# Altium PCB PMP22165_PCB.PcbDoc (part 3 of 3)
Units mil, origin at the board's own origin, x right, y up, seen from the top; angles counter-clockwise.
Board outline 3700 x 3000 mil, 4 copper layers (Top Layer, Signal Layer 1, Signal Layer 2, Bottom Layer), stack 61.634 mil thick; 232 components, 104 nets, 594 pads, 232 vias.
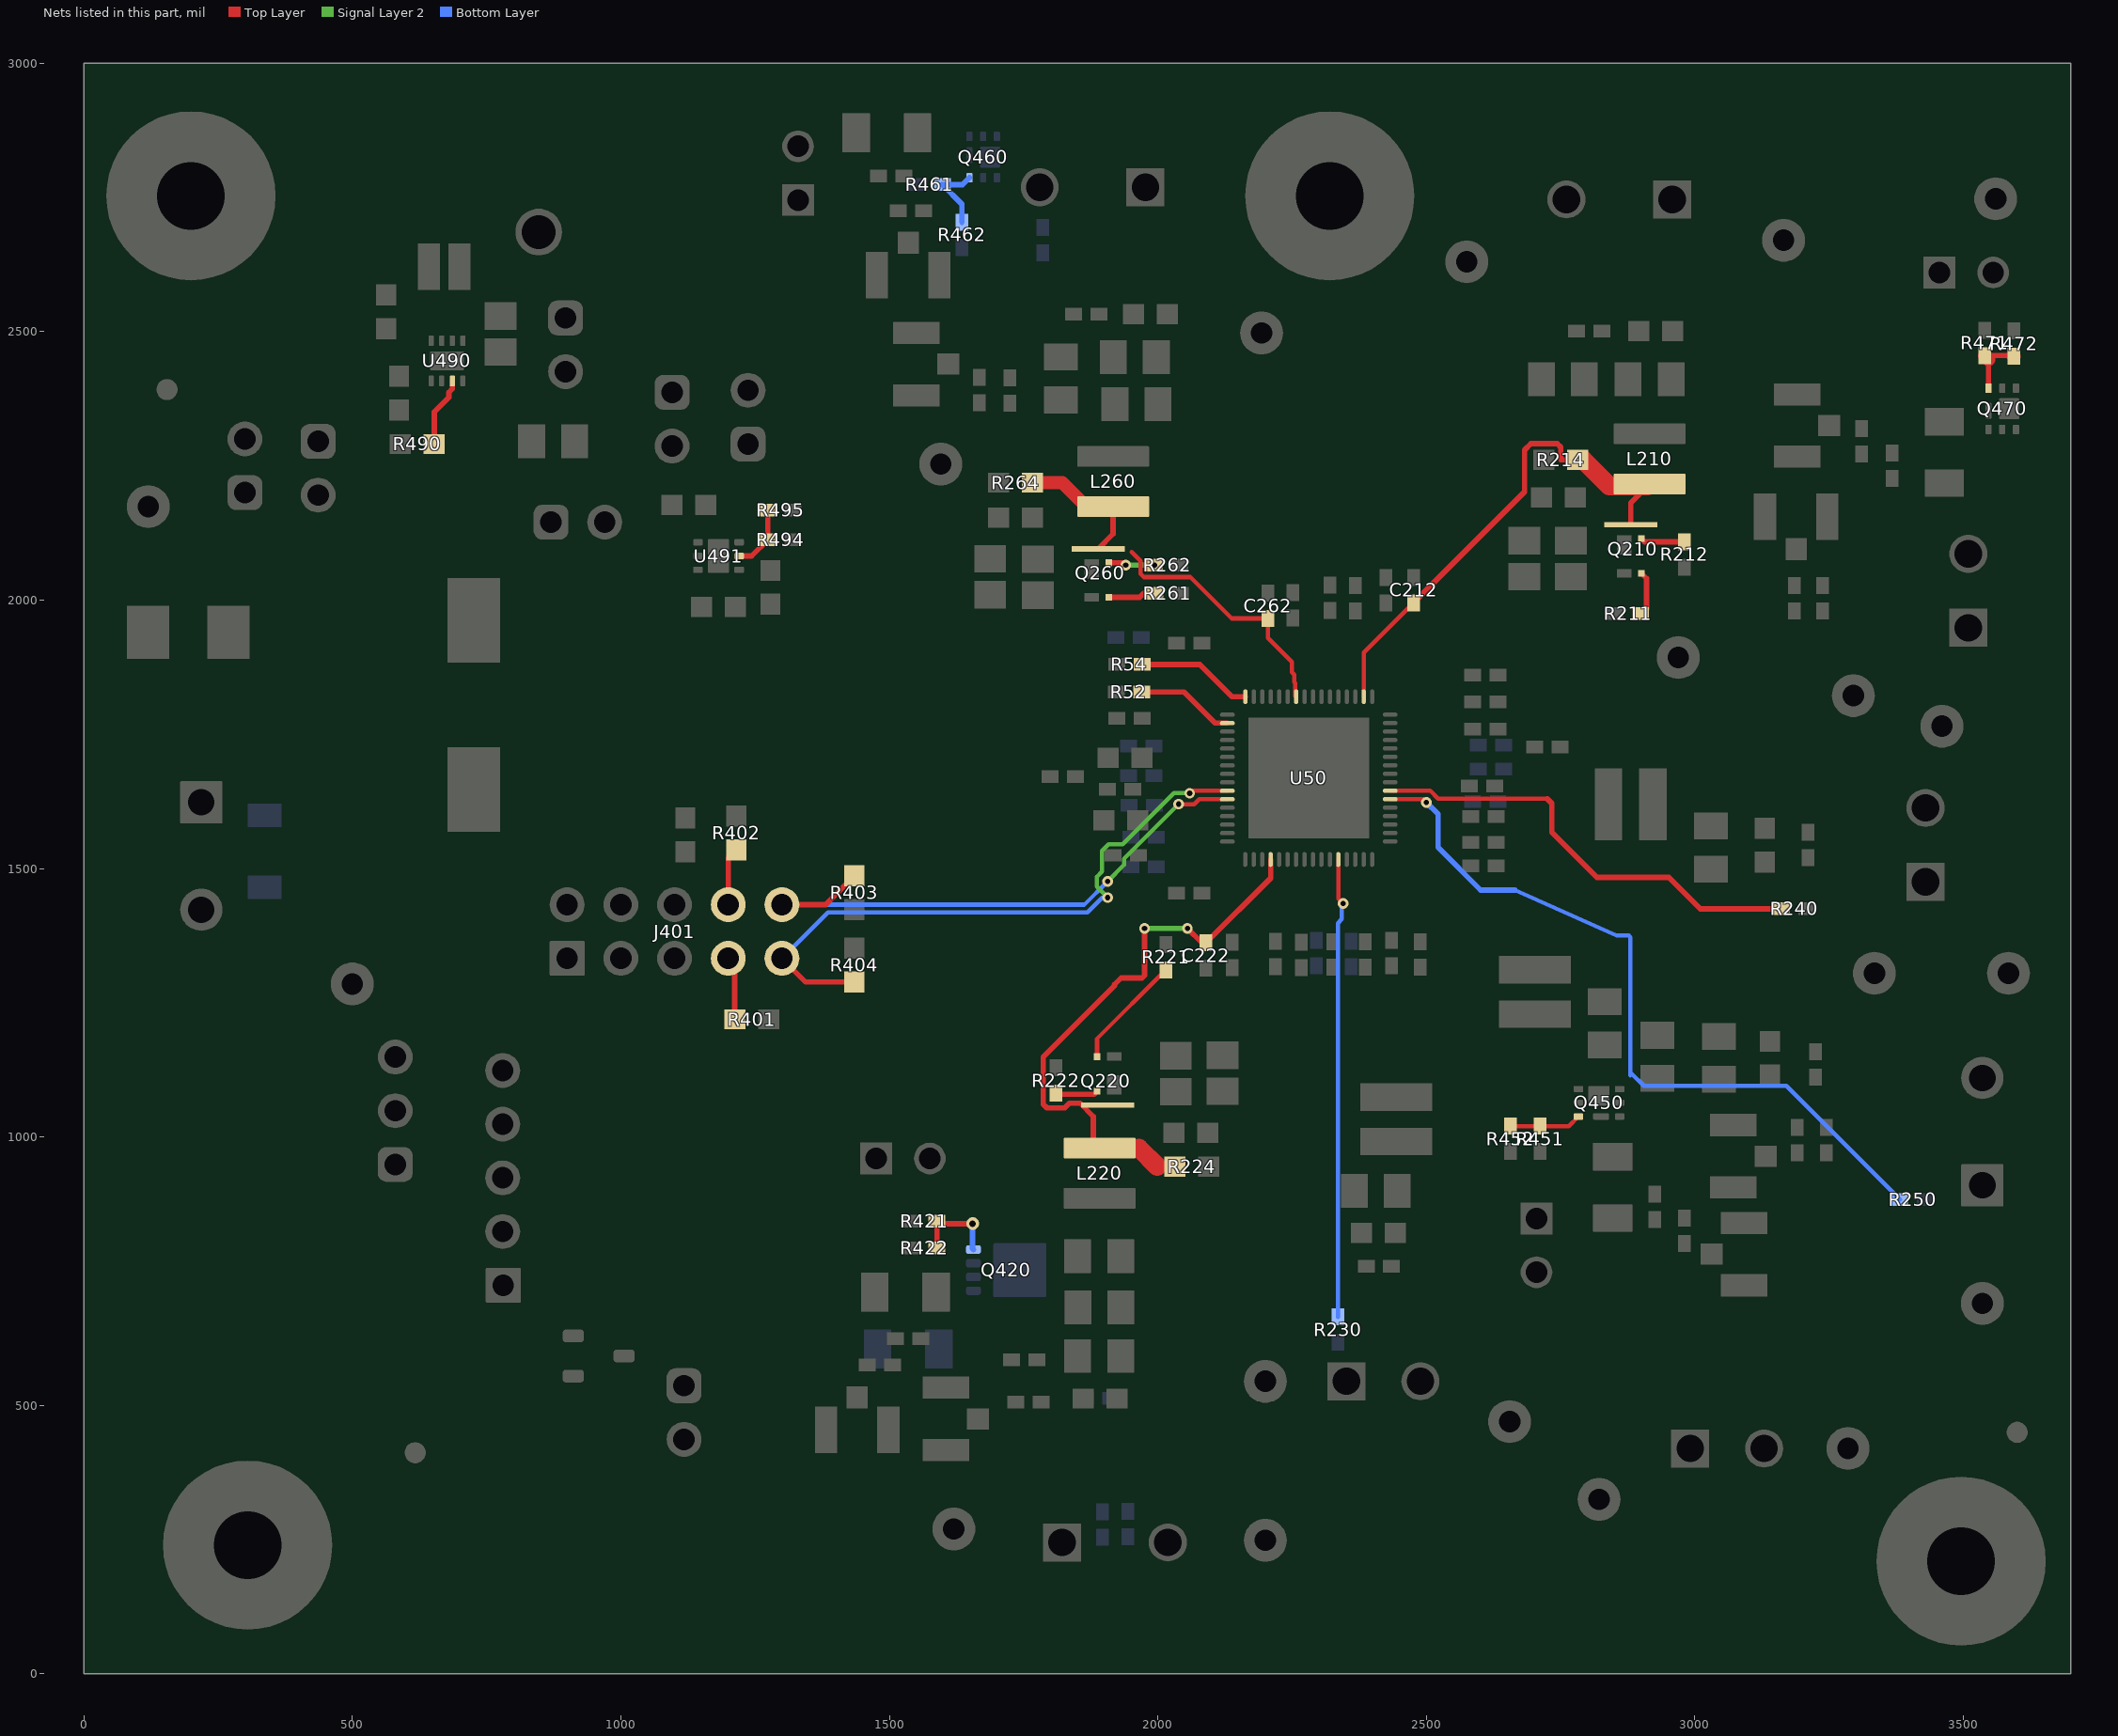
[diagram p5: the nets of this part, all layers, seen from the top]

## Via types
v1: diameter 19.68, hole 10, Top Layer to Bottom Layer, 141 vias
v2: diameter 23.62, hole 11.81, Top Layer to Bottom Layer, 63 vias
v3: diameter 19.68, hole 7.87, Top Layer to Bottom Layer, 27 vias
v4: diameter 19.68, hole 7.87, Top Layer to Bottom Layer, tented both sides, 1 vias

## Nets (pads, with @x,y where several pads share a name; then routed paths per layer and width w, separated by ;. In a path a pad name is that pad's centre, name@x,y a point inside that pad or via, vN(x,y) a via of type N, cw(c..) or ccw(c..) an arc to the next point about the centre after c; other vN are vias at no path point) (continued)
NetQ210_1: Q210.1 R211.2 | length 70.3
  Top Layer w10: Q210.1@2900.28,2049.97 2909.94,2040.31 R211.2@2909.94,1983.62
NetQ210_4: Q210.4 R212.2 | length 82.2
  Top Layer w10: Q210.4@2900.28,2114.4 2906.23,2108.45 R212.2@2980,2108.45
NetQ220_1: Q220.1 R221.2 | length 214.9
  Top Layer w8: Q220.1@1886.8,1149.59 1886.8,1183.18 R221.2@2015,1311.38
NetQ220_4: Q220.4 R222.2 | length 82.5
  Top Layer w10: R222.2@1806.62,1079.61 1881.25,1079.61 Q220.4@1886.8,1085.16
NetQ260_1: Q260.1 R261.2 | length 88.9
  Top Layer w10: Q260.1@1908.69,2004.93 1965.95,2004.93 1973.63,2012.6 R261.2@1994.38,2012.6
NetQ260_4: Q260.4 R262.2 | length 87
  Top Layer w10: Q260.4@1908.69,2069.35 1935.71,2069.35 v1(1940.07,2065)
  Signal Layer 2 w10: v1(1940.07,2065) v1(1993.86,2065)
NetQ420_4: Q420.4 R421.2 R422.2 | length 166.2
  Top Layer w10: R422.2@1588.32,793.73 1588.62,794.03 R421.2@1588.62,842.92 1593.06,838.48 v2(1655,838.48)
  Bottom Layer w10: v2(1655,838.48) 1655,792.01 Q420.4@1656.56,790.45
NetQ450_3: Q450.3 R451.2 R452.2 | length 133.8
  Top Layer w8: R452.2@2656.61,1020.24 R451.2@2711.61,1020.24 2765.23,1020.24 Q450.3@2783.04,1038.05
NetQ460_3: Q460.3 R461.2 R462.2 | length 140.9
  Bottom Layer w10: R462.2@1635,2703.62 1635,2737.25 R461.2@1598.62,2773.63 1636.12,2773.63 Q460.3@1649.11,2786.61
NetQ470_3: Q470.3 R471.2 R472.2 | length 118.4
  Top Layer w10: R471.2@3539.5,2455.25 R472.2@3592.37,2455.25 ; Q470.3@3546.61,2394.58 R471.2@3546.61,2448.13
  Top Layer w25: R471.2@3539.5,2455.25 R471.2@3546.61,2448.13 ; R472.2@3592.37,2455.25 R472.2@3593.75,2453.87
NetR52_1: R52.1 U50.50 | length 183.6
  Top Layer w10: R52.1@1969.76,1828.86 2048.77,1828.86 2106.53,1771.1 2129.01,1771.1 U50.50@2129.32,1770.79
NetR54_1: R54.1 U50.48 | length 217.3
  Top Layer w10: R54.1@1970.38,1880 2078,1880 2138,1820 U50.48@2162.78,1820
NetR230_1: R230.1 U50.12 | length 859.7
  Top Layer w8: U50.12@2336.01,1516.85 2336.01,1443.99 v1(2345,1435)
  Bottom Layer w8: R230.1@2335,665.04 2335,1398.18 2342.57,1405.76 2342.57,1432.57 v1(2345,1435)
NetR240_1: R240.1 U50.23 | length 851.6
  Top Layer w8: U50.23@2432.47,1644.8 2507.23,1644.8 2521.89,1630.15 2724.85,1630.15
  Top Layer w10: 2724.85,1630.15 2733.54,1621.46 2733.54,1567.52 2817.51,1483.55 2951.45,1483.55 3010,1425 R240.1@3161.38,1425
NetR250_1: R250.1 U50.22 | length 1427.7
  Top Layer w8: U50.22@2432.47,1629.05 2494.11,1629.05 v1(2500,1623.17)
  Bottom Layer w8: 2665,1460 2855,1375 2876.95,1375 2880,1371.95 2880,1115 ; 2881.95,1118.05 2905,1095 3170.21,1095 R250.1@3382.02,883.19
  Bottom Layer w10: v1(2500,1623.17) 2521.69,1601.48 2521.69,1539.36 2601.05,1460 2665,1460
NetR490_1: R490.1 U490.3 | length 131.5
  Top Layer w10: R490.1@652.64,2290.44 652.64,2350.24 679.77,2377.37 679.77,2386.86 686.14,2393.23 U490.3@686.14,2408.07
NetR494_1: R494.1 R495.2 U491.2 | length 120.8
  Top Layer w10: U491.2@1220.26,2082.03 1243.62,2082.03 R494.1@1273.62,2112.03 R495.2@1273.62,2167.03
optional-control-input: J401.7 R401.1 | length 118.6
  Top Layer w10: J401.7@1200,1332.67 1212.03,1320.64 R401.1@1212.03,1219.05
PMB_ALERT#: J401.8 R402.1 | length 108.2
  Top Layer w10: J401.8@1200,1432.67 1200,1519.68 R402.1@1215,1534.68
PMB_CLK: J401.9 R404.1 U50.58 | length 1186.6
  Top Layer w8: v1@2057,1646.05 2058.25,1644.8 U50.58@2129.32,1644.8
  Top Layer w10: J401.9@1300,1332.67 1344.16,1288.5 R404.1@1435,1288.5
  Signal Layer 2 w8: v1(1906.38,1446) 1886.04,1466.34 1886.04,1484.43 1896.04,1494.43 1896.04,1533.02 1907.95,1544.94 1934.6,1544.94 2030,1640.34 2058.66,1640.34 v1(2059,1640)
  Bottom Layer w8: J401.9@1300,1332.67 1385.5,1418.17 1869.05,1418.17 1896.88,1446 v1(1906.38,1446)
PMB_DIO: J401.10 R403.1 U50.59 | length 1075.2
  Top Layer w8: v1(2038.43,1620) 2038.77,1619.66 2067.43,1619.66 2076.82,1629.05 U50.59@2129.32,1629.05
  Top Layer w10: J401.10@1300,1432.67 1381.17,1432.67 R403.1@1435,1486.5
  Signal Layer 2 w8: v1(1906.38,1476) 1936.72,1506.34 1936.72,1518.29 v1(2038.43,1620)
  Bottom Layer w8: J401.10@1300,1432.67 1863.05,1432.67 v1(1906.38,1476)
SW1: C212.1 L210.1 Q210.5 R214.2 U50.34 | length 944.2
  Top Layer w8: U50.34@2383.26,1820 2383.26,1902.15 C212.1@2476.1,1995
  Top Layer w10: C212.1@2476.1,1995 2682.8,2201.7 2682.8,2279.58 2694.54,2291.31 2743.43,2291.31 2750.17,2284.58 2750.17,2261.11 R214.2@2781.98,2261.11 ; Q210.5@2880.48,2140.25 2880.48,2181.11 2911.46,2212.09 L210.1@2915.48,2216.11
  Top Layer w35: R214.2@2791.85,2261.11 2840.88,2212.09 L210.1@2911.46,2212.09
SW2: C222.1 L220.1 Q220.5 R224.2 U50.4 | length 1087
  Top Layer w10: 1964.77,979.31 L220.1@1891.49,979.31 1879.9,990.9 1879.9,1038.21 1855,1063.11 1835.55,1063.11 1826.57,1054.13 1793.43,1054.13 1786.69,1060.87 1786.69,1149.13 1919.11,1281.56 1919.11,1283.84 1931.62,1296.34 1970.52,1296.34 1975,1300.83 v1(1975,1388.4) ; 1999.08,945 R224.2@2031.46,945 ; v1(2055,1388.4) 2081.78,1361.62 C222.1@2089.5,1361.62 2210.03,1482.15 U50.4@2210.03,1516.85
  Top Layer w35: 1964.77,979.31 1999.08,945
  Signal Layer 2 w10: v1(1975,1388.4) v1(2055,1388.4)
SW6: C262.1 L260.1 Q260.5 R264.2 U50.42 | length 745.7
  Top Layer w8: 1951.21,2089.25 1967.62,2072.84 1967.62,2048.84 1973.77,2042.69 2060.42,2042.69 2137.43,1965.68 C262.1@2205,1965.68 2205,1929.27 2249.84,1884.43 2249.84,1865.22 2253.97,1861.09 2253.97,1847.09 2256.02,1845.03 2256.02,1821.25 U50.42@2257.27,1820
  Top Layer w10: L260.1@1866.55,2174.01 L260.1@1916.69,2174.01 1916.69,2123.01 Q260.5@1888.88,2095.2
  Top Layer w25: R264.2@1766.18,2218.63 1821.93,2218.63 L260.1@1866.55,2174.01
pads on no net: FID1.1 FID2.1 FID3.1 H1.1 H2.1 H3.1 H4.1 H5.0 H6.0 H7.0 H8.0 J401.1 J401.2 J401.3 J401.4 J401.5 J422.2@1499.06,455 J422.3@1380.94,455 J423.2@1605,415.94 J423.3@1605,534.06 J452.2@3091.43,840.96 J452.3@3091.43,722.85 J453.2@3071.57,905.19 J453.3@3071.57,1023.3 J462.2@1594.06,2605.44 J462.3@1475.94,2605.44 J463.2@1550,2380.3 J463.3@1550,2498.41 J472.2@3190.15,2265.94 J472.3@3190.15,2384.06 J473.2@3129.45,2155.03 J473.3@3247.56,2155.03 LBL1.0 Q420.9A Q420.9B Q420.9C Q420.9D Q450.0 Q460.0 Q470.0 U50.9 U50.47 U50.49 U50.51 U490.9@658.58,2445.48 U490.9@694.02,2445.48 U491.7@1181.87,2064.32 U491.7@1181.87,2099.75

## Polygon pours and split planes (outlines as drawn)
NetC471_1 on Top Layer "TOP_LAYER_NETC471_1_P036" (solid, remove dead copper, pour order 36): 3347.5,2260 3349.88,2262.38 3349.88,2313.38 3410.94,2313.38 3417.06,2319.5 3417.06,2369.49 3556.38,2369.49 3550.57,2363.68 3550.57,2298.71 3444.68,2298.71 3443.39,2300 3443.39,2260 3348.61,2260 3347.5,2261.11
GND on Top Layer "TOP_LAYER_GND_P048" (solid, remove dead copper, pour order 48): 34.42,2945.8 44.42,2955.8 3659.42,2955.8 3659.42,25.8 3629.42,-4.2 3589.42,35.8 29.42,35.8 34.42,40.8
2v5_IO on Top Layer "TOP_LAYER_2V5_IO_P042" (solid, remove dead copper, pour order 42): 2893.2,1685 2895,1683.2 2895,1549.02 2920.42,1549.02 3009.43,1460 3357.02,1460 3382.02,1435 3484.22,1435 3484.22,1515.68 3475.31,1524.59 3237.37,1524.59 3221.97,1540 2986.85,1540 2957.51,1569.34 2957.51,1690 2894.72,1690 2893.2,1688.48
0v88 on Top Layer "TOP_LAYER_0V88_P040" (solid, remove dead copper, pour order 40): 2639.02,1250 2760,1129.02 2760,1060.87 2977.22,1060.87 2986.36,1070 3155,1070 3155,1008.69 3168.69,995 3355,995 3490,860 3490,831.49 3624.72,898.85 3375.3,1087.77 3320,1087.77 3256.65,1151.12 2893.2,1151.12 2893.2,1194.17 2872.37,1215 2781.98,1215 2781.98,1249.04 2779.24,1251.77 2777.47,1250
1v1_IO on Top Layer "TOP_LAYER_1V1_IO_P038" (solid, remove dead copper, pour order 38): 2515,1022.32 2515,960 2410,960 2405,955 2405,475 2300,475 2295,480 2310,495 2310,946.61 2361.61,946.61 2361.61,955 2362.62,962.38 2362.62,1022.32 2508.39,1022.32 2510,1023.92
1v5 on Top Layer "TOP_LAYER_1V5_P032" (solid, remove dead copper, pour order 32): 1962.33,910 1687.64,910 1687.64,702.36 1747.3,642.7 1760,642.7 1760,195.19 1756.29,191.48 1895,191.48 1895,838.48 1911.52,855 1962.33,855
12V_B on Top Layer "TOP_LAYER_12V_B_P026" (solid, remove dead copper, pour order 26): 211.16,2099.75 211.16,1860.82 216.98,1855 990,1855 995,1860 995,2063.19 1000,2068.19 998.84,2069.35 233.34,2069.35 233.34,2080.01 213.35,2100
12V on Top Layer "TOP_LAYER_12V_P024" (solid, remove dead copper, pour order 24): 65,2000 61.37,1996.37 61.37,1885 75,1885 75,1565.98 396.68,1565.98 390,1572.67 390,1675 221.16,1675 167.91,1728.26 167.91,1993.22 174.68,2000
12V_B on Top Layer "TOP_LAYER_12V_B_P020" (solid, remove dead copper, pour order 20): 1903.77,1200 1906.11,1197.66 2178.53,1197.66 2178.53,1122.53 2180,1121.06 2176.59,1117.66 1953.23,1117.66 1930.89,1140 1900.7,1140 1900.7,1196.05 1905,1200.34
SW2 on Top Layer "TOP_LAYER_SW2_P018" (solid, remove dead copper, pour order 18): 1850,1069.33 1850,1007.66 1821.75,1007.66 1819.41,1010 1819.41,954.65 1963.69,954.65 1993.34,925 2051.46,925 2055,921.46 2055,973.54 1970.54,973.54 1959.04,985.04 1959.04,1066.26 1955.3,1070 1954.63,1069.33
3v3 on Top Layer "TOP_LAYER_3V3_P014" (solid, remove dead copper, pour order 14): 2905,2371.11 2900.28,2375.83 2900.28,2462.69 2920,2482.41 2919.85,2580.15 2915,2585 2915.48,2585.48 2915.48,2639.8 2765,2790.28 2764.24,2789.53 2718.98,2789.53 2718.98,2703.15 2767.13,2655 2800.1,2591.75 2807.28,2465 2761.47,2465 2765,2461.47 2765,2371.11 2766.94,2371.11 2848.39,2289.65 2850.36,2291.62 2988.27,2291.62 2988.27,2334.64 2968.97,2353.94 2905.59,2353.94 2905.59,2372.41 2903,2375
SW1 on Top Layer "TOP_LAYER_SW1_P012" (solid, remove dead copper, pour order 12): 2829.3,2135 2931.66,2135 2931.66,2145 2984.07,2197.4 2982.91,2198.56 2982.91,2242.41 2978.21,2247.11 2819.51,2247.11 2819.51,2290.66 2801.19,2290.66 2797.72,2290.66 2757.44,2290.66 2757.44,2236.46 2767.79,2226.11 2830,2226.11 2830,2135.7
12V_B on Top Layer "TOP_LAYER_12V_B_P010" (solid, remove dead copper, pour order 10): 2605.94,2070 2606.59,2069.35 2880.48,2069.35 2880.48,2008.85 2879.02,2007.39 2605.94,2007.39
1v2 on Top Layer "TOP_LAYER_1V2_P008" (solid, remove dead copper, pour order 8): 1981.8,2246.12 1981.38,2246.54 1981.38,2286.72 1957.86,2286.72 1950,2294.59 1950,2492.73 1958.7,2492.73 1980,2514.02 1976.84,2517.19 1976.84,2651.37 1810.37,2817.84 1739.08,2817.84 1739.08,2628.31 1740,2627.39 1871.57,2627.39 1871.57,2246.12 1980.32,2246.12 1981.38,2247.17
12V_B on Top Layer "TOP_LAYER_12V_B_P006" (solid, remove dead copper, pour order 6): 1595,2034.79 1595.83,2033.97 1837.73,2033.97 1860,2011.69 1893.55,2011.69 1893.55,1965 1595,1965
SW6 on Top Layer "TOP_LAYER_SW6_P000" (solid, remove dead copper, pour order 0): 1950,2085.91 1979.5,2115.41 1979.5,2192.03 1848.53,2192.03 1793.39,2247.17 1750,2247.17 1750,2211.34 1757.71,2203.63 1819.68,2203.63 1837.7,2185.6 1837.7,2085 1949.09,2085 1950.59,2086.5
GND on Signal Layer 2 "SIGNAL_LAYER_2_GND_P050" (solid, remove dead copper, pour order 50): 35,2975 35,35 3670,35 3670,2965 3660,2975
3v3 on Signal Layer 2 "SIGNAL_LAYER_2_3V3_P030" (solid, remove dead copper, pour order 30): 2665,2810 2660,2805 2660,2400 2885,2400 2910,2375 2910,1760 2510,1760 2510,1465 3100,1465 3115,1480 3105,1490 3105,2595 2880,2595 2855,2620 2855,2810
12V_B on Signal Layer 2 "SIGNAL_LAYER_2_12V_B_P028" (solid, remove dead copper, pour order 28): 813.54,2070 2792.1,2070 2792.1,1940 1832.19,1940 1832.19,1272.81 1875,1230 2195,1230 2195,1115.1 1763.22,1122.5 1667.78,1759.03 1586.81,1840 813.54,1840
GND on Bottom Layer "BOTTOM_LAYER_GND_P054" (solid, remove dead copper, pour order 54): 35,2975 35,50 30,45 40,35 3680,35 3680,2970 3675,2975
1v2 on Bottom Layer "BOTTOM_LAYER_1V2_P044" (solid, remove dead copper, pour order 44): 1815,2885 1815,2730 1820,2725 1665,2725 1665,2880 1660,2885
NetC421_1 on Bottom Layer "BOTTOM_LAYER_NETC421_1_P034" (solid, remove dead copper, pour order 34): 1670,557.36 1540,557.36 1550,567.36 1550,777.66 1667.66,777.66 1670,780
GND on Signal Layer 1 "SIGNAL_LAYER_1_GND_P046" (solid, remove dead copper, pour order 46): 40,2960 50,2950 50,40 3670,40 3660,50 3660,2965 45,2965

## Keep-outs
Keep-Out Layer:
  text ".Layer_Name" at 577,-858.49 h60

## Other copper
Top Layer:
  text ".Layer_Name" at 577,-858.49 h60
Bottom Layer:
  text ".Layer_Name" at 577,-858.49 h60

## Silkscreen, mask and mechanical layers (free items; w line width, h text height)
Top Overlay:
  text "Optional on-board 5V" at 455,2885 h72.83
  text "1.2V" at 1667.57,2815 h80 r90
  text "jumper J491, J492, J493 to use" at 395,2785 h60
  text "GND" at 2140,2763.63 h72.83 r90
  text "3.3V" at 2629.57,2738.21 h80 r90
  text "GND" at 3131.61,2714.62 h72.83 r90
  text "dyn_1.2V" at 1250,2700 h60 r90
  text "dyn_1.5Vaux" at 3257.91,2680 h50
  text "optional" at 1060,2591.46 h50
  text "Isense" at 1435,2559.99 h40 r90
  text "main 0.78V \"stand-in\"" at 970,2540 h50
  text "jumper J494-5-6 to use" at 965,2485 h50
  text "1.5Vaux" at 3120,2469.03 h55
  text "Isense" at 3129.45,2425.44 h50
  text "1.2V Vsns" at 1462.27,2345.44 h40 r90
  text "Vsns 1.5Vaux" at 3109.43,2081.13 h50 r270
  text "GND" at 3685,2068.26 h50 r90
  text "All Good" at 3035,1943.31 h50 r270
  text "1.5V aux" at 3470,1821.97 h60
  text "12Vin" at 190,1750 h72.83
  text "GND" at 3260,1705 h72.83
  text "Main Input" at 450,1640 h72.83 r270
  text "2.5V" at 3398.31,1332.67 h80
  text "GND" at 245.06,1251.77 h72.83
  text "PMBus comm." at 875,1242.68 h50
  text "GND" at 3390.07,1230 h72.83
  text "GND" at 615,1130 h50
  text "GND" at 881.48,1113.27 h60
  text "dyn_1.5V" at 1403.5,1030 h60
  text "IRQB" at 620,1023.92 h50
  text "5V" at 887.11,1001.03 h60
  text "0.88V" at 2955,936.69 h50 r90
  text "CTL4" at 620,934.07 h50
  text "3v3 Good" at 869.08,913.71 h60
  text "dyn_0.88V" at 2610,899.46 h50 r270
  text "Vsense" at 2995,894.46 h55 r90
  text "Interface to" at 1169.7,882.54 h60 r90
  text "programming" at 480,829.74 h40
  text "5V Good" at 880,810.11 h60
  text "0.88V" at 3480.48,750.94 h80
  text "0.78V Good" at 869.08,696.7 h60
  text "TPS53681EVM-002" at 1237.11,675 h60 r90
  text "0.88V Isense" at 3028.26,655 h55
  text "'.PRJ_Number'.PCB_Rev" at 455,495 h108.27 r90
  text "jumper to" at 1220.26,355 h60 r90
  text "Vsns" at 1545,345 h60
  text "Isns" at 1395,335 h60
  text "power down" at 1270,318.71 h60 r90
  text "1.1V" at 2386.54,260 h80 r90
  text "GND" at 2535,260 h72.83 r90
  text "GND" at 3175,125 h72.83 r90
  text "GND" at 2130,67.83 h72.83
  text "1.5V" at 1565,65 h80
  text "For evaluation only;" at 495,55 h40
  text "not FCC approved" at 816.19,55 h40
  text "for resale" at 1115,55 h40
  text "3.3Vaux" at 3000,50 h70 r90
  text ".Layer_Name" at 577,-858.49 h60
Bottom Overlay:
  text ".Layer_Name" at 577,-858.49 h60
Top Paste:
  text ".Layer_Name" at 577,-858.49 h60
Bottom Paste:
  text ".Layer_Name" at 577,-858.49 h60
Top Solder:
  text ".Layer_Name" at 577,-858.49 h60
  text ".Layer_Name" at 577,-858.49 h60
Bottom Solder:
  text ".Layer_Name" at 577,-858.49 h60
Drill Guide:
  text ".Layer_Name" at 577,-858.49 h60
M1 Board Outline:
  lines w20: -10,0 ccw(c0,0) 0,-10 ; -10,0 ccw(c0,0) 0,-10 ; -10,0 -10,3000 ; -10,3000 cw(c0,3000) 0,3010 ; -10,3000 cw(c0,3000) 0,3010 ; 0,-10 3700,-10 ; 0,3010 3700,3010 ; 3700,-10 ccw(c3700,0) 3710,0 ; 3700,-10 ccw(c3700,0) 3710,0 ; 3700,3010 cw(c3700,3000) 3710,3000 ; 3700,3010 cw(c3700,3000) 3710,3000 ; 3710,0 3710,3000 ; 10,10 3690,10 3690,2990 10,2990 10,10 ; 26.23,26.23 26.23,2973.77 3673.77,2973.77 3673.77,26.23 26.23,26.23
  text ".Layer_Name" at 577,-858.49 h60
M2 Board Dimensions:
  rectangle: 0,-275 125,-150
  rectangle: 125,-400 500,-275
  lines w7: 0,-275 1000,-275 ; 125,-400 125,-150 ; 250,-400 250,-150 ; 500,-400 500,-150 ; 750,-400 750,-150 ; 0,-400 1000,-400 1000,-150 0,-150 0,-400
  text ".Layer_Name" at 577,-858.49 h60
M3 3D STEP Top:
  text ".Layer_Name" at 577,-858.49 h60
M4 3D STEP Bottom:
  text ".Layer_Name" at 577,-858.49 h60
M5 Assembly Top:
  lines w10: -292,-930.17 6308,-930.17 ; -292,-726.83 6310,-726.83 ; -292,-523.5 -292,-1133.5 3713,-1133.5 6310,-1133.5 6310,-523.5 -291.5,-523.5 -291.5,-1133.5 1284,-1133.5 ; 2173,-1133.5 2173,-523.5 ; 3440,-726.83 3440,-523.5 ; 4280,-726.83 4280,-523.5 ; 4902,-1140 4902,-937.17
  text "COMPONENTS MARKED 'DNP' SHOULD NOT BE POPULATED." at 1153.5,-318.5 h60
  text "ASSEMBLY VARIANT:" at 1153,-434 h60
  text ".VariantName" at 2189,-434 h60
  text "PCB VIEWED FROM TOP SIDE" at -228.5,-655.67 h60
  text "BOARD #:" at 2248,-655.67 h60
  text ".PRJ_Number" at 2793.5,-655.67 h60
  text "REV:" at 3638,-655.67 h60
  text ".PCB_Rev" at 3929.5,-655.67 h60
  text "SVN REV:" at 4476,-655.67 h60
  text ".VersionControl_RevNumber" at 4982,-655.67 h60
  text "TID #:" at 2248,-859 h60
  text ".TID" at 2793.5,-859 h60
  text "PLOT NAME =" at -228.5,-1064.34 h60
  text ".plot_File_Name" at 577,-1064.34 h60
  text "GENERATED    :" at 2250,-1064.34 h60
  text ".Print_Date" at 3119.5,-1064.34 h60
  text ".Print_Time" at 3848.5,-1064.34 h60
  text "TEXAS INSTRUMENTS" at 5113,-1064.34 h60
M6 Assembly Bottom:
  lines w10: -292.5,-727.33 6309.5,-727.33 ; -290.5,-930.67 6309.5,-930.67 ; 1115.5,-1140.5 1115.5,-937.67 ; 1737.5,-727.33 1737.5,-524 ; 2577.5,-727.33 2577.5,-524 ; 3844.5,-1134 3844.5,-524 ; 4733.5,-1134 6309,-1134 6309,-524 -292.5,-524 -292.5,-1134 2304.5,-1134 6309.5,-1134 6309.5,-524
  text "COMPONENTS MARKED 'DNP' SHOULD NOT BE POPULATED." at 6102,-318 h60
  text ".VariantName" at 5058,-434 h60
  text "ASSEMBLY VARIANT:" at 6097,-434 h60
  text ".VersionControl_RevNumber" at 1035.5,-656.17 h60
  text "SVN REV:" at 1541.5,-656.17 h60
  text ".PCB_Rev" at 2088,-656.17 h60
  text "REV:" at 2379.5,-656.17 h60
  text ".PRJ_Number" at 3224,-656.17 h60
  text "BOARD #:" at 3769.5,-656.17 h60
  text "PCB VIEWED FROM BOTTOM SIDE" at 6246,-656.17 h60
  text ".TID" at 3224,-859.5 h60
  text "TID #:" at 3769.5,-859.5 h60
  text "TEXAS INSTRUMENTS" at 904.5,-1064.84 h60
  text ".Print_Time" at 2169,-1064.84 h60
  text ".Print_Date" at 2898,-1064.84 h60
  text "GENERATED    :" at 3767.5,-1064.84 h60
  text ".plot_File_Name" at 5440.5,-1064.84 h60
  text "PLOT NAME =" at 6246,-1064.84 h60
M9 Title Sheet:
  drawing of 57 lines, arcs and shapes, not listed
  text "1" at 739.84,8036.5 h70
  text "2" at 3235.5,8036.5 h70
  text "3" at 5724.84,8036.5 h70
  text "4" at 8231.51,8036.5 h70
  text "5" at 10730.5,8036.5 h70
  text "6" at 13235.5,8036.5 h70
  text "A" at -416.5,6893.5 h70
  text "A" at 14383.5,6893.5 h70
  text "B" at -416.5,4513.5 h70
  text "B" at 14383.5,4513.5 h70
  text "C" at -416.5,2138.5 h70
  text "C" at 14383.5,2138.5 h70
  text "PROJECT TITLE:" at 11343.5,277.5 h45
  text ".PRJ_Title" at 11393.5,144.17 h70
  text "DESIGNED FOR:" at 11343.5,-23.5 h45
  text ".PRJ_Customer" at 11393.5,-163.5 h70
  text "D" at -416.5,-231.5 h70
  text "D" at 14383.5,-231.5 h70
  text "FILE NAME:" at 11343.5,-323.5 h45
  text ".PCB_File_Name_No_Path" at 11393.5,-443.5 h70
  text "Texas Instruments (TI) and/or its licensors do not warrant the accuracy or completeness of this specification" at 6374,-605.34 h45
  text "ENGINEER:" at 11343.5,-613.5 h45
  text "LAYOUT BY:" at 12848.5,-613.5 h45
  text "or any information contained therein. TI and/or its licensors do not warrant that this design will meet" at 6329.01,-718 h45
  text ".PRJ_Engineer" at 11393.5,-768.49 h70
  text ".PCB_Layout" at 12899,-768.49 h70
  text "the specifications, will be suitable for your application or fit for any particular purpose, or will operate in" at 6329.01,-830.67 h45
  text ".Layer_Name" at 577,-858.49 h60
  text "ALTIUM DESIGNER VERSION:" at 12848.5,-923.5 h45
  text "an implementation. TI and/or its licensors do not warrant that the design is production worthy. You should" at 6329.01,-943.33 h45
  text "completely validate and test your design implementation to confirm the system functionality for your application." at 6374,-1056 h45
  text ".print_Scale" at 11393.5,-1056.83 h70
  text ".Application_BuildNumber" at 12899,-1056.83 h70
  text "1" at 739.84,-1263.5 h70
  text "2" at 3235.5,-1263.5 h70
  text "3" at 5724.84,-1263.5 h70
  text "4" at 8231.51,-1263.5 h70
  text "5" at 10730.5,-1263.5 h70
  text "6" at 13235.5,-1263.5 h70
M10 Fab Notes:
  drawing of 189 lines, arcs and shapes, not listed
  text "DESIGN INFORMATION" at 12382.02,6356.17 h60
  text "MIN. TRACK WIDTH:" at 11737.46,6224.05 h60
  text "8" at 12833.7,6224.05 h60
  text "MIL" at 12988.46,6224.05 h60
  text "MIN. CLEARANCE:" at 11737.46,6099.92 h60
  text "0.2" at 12773.7,6099.93 h60
  text "mm" at 12988.46,6099.92 h60
  text "MIN. VIA PAD SIZE:" at 11737.46,5975.8 h60
  text "24" at 12803.71,5975.8 h60
  text "MIL" at 12988.46,5975.8 h60
  text "0.05mm (2MIL)" at 12432.46,5845.9 h60
  text "MINIMUM ANNULAR RING" at 11408.23,5837.67 h60
  text "EXTERNAL" at 13140.46,5837.67 h60
  text "PER" at 11608.23,5727.55 h60
  text "IPC-D-275 CLASS 2 LEVEL C" at 11828.23,5727.54 h60
  text "MIL, HOLES" at 13316.46,5627.07 h60
  text "+/-" at 12924,5618.48 h60
  text "+/-" at 13778,5618.48 h60
  text "REGISTRATION TOLERANCES:" at 11408.23,5617.42 h60
  text "METAL" at 12608,5617.42 h60
  text "5" at 13184.2,5617.42 h60
  text "3" at 14017.2,5617.42 h60
  text "MIL" at 14133.46,5617.42 h60
  text "HOLE SIZE TOLERANCE (UNLESS OTHERWISE SPECIFIED):" at 11408.23,5519.1 h60
  text "+/-" at 13778,5516.23 h60
  text "3" at 14017.2,5515.17 h60
  text "MIL" at 14133.46,5515.17 h60
  text "MATERIAL:" at 11333.46,5377.52 h60
  text "FR-4 High Tg" at 12319.9,5249 h60
  text "X" at 12175.46,5241.01 h60
  text "FR-408" at 11754.46,5236.49 h60
  text "OTHER" at 13242.46,5236.49 h60
  text "62 MIL (1.6mm) +/-10%" at 12074.56,5093.46 h60
  text "X" at 11954.46,5091.01 h60
  text "THICKNESS:" at 11408.23,5085.24 h60
  text "OTHER" at 13359.46,5085.24 h60
  text "TOLERANCE:" at 11408.23,4946.92 h60
  text "X" at 12256.46,4946.92 h60
  text "ANSI IPC-6012 TYPE 3 CLASS 2" at 12434.48,4946.92 h60
  text "OTHER +/-" at 12434.46,4802.73 h60
  text "BOW & TWIST:" at 11408.23,4657.54 h60
  text "X" at 12256.46,4657.54 h60
  text "ANSI IPC-6012 TYPE 3 CLASS 2" at 12434.48,4657.54 h60
  text "OTHER +/-" at 12434.46,4510.85 h60
  text "DRILLING:" at 11333.46,4380.23 h60
  text "NC_DRILL FILES" at 13094.46,4275.04 h60
  text "REFERENCE:" at 11408.23,4271.1 h60
  text "X" at 12065.46,4271.01 h60
  text "AS SHOWN" at 12243.46,4271.1 h60
  text "X" at 12966.46,4271.1 h60
  text "OTHER" at 13392.46,4128.85 h60
  text "PTH COPPER THICKNESS:" at 11407.91,4125.32 h60
  text "X" at 12547.14,4125.32 h60
  text "20-30 um" at 12675.14,4125.32 h60
  text "BOARD FINISH:" at 11333.46,3977.73 h60
  text "SILKSCREEN:" at 11488.68,3867.6 h60
  text "X" at 12446.46,3867.6 h60
  text "TOP" at 12563.46,3867.6 h60
  text "X" at 12956.46,3867.6 h60
  text "BOTTOM" at 13074.46,3867.6 h60
  text "SILKSCREEN COLOR:" at 11488.68,3712.41 h60
  text "X" at 12445.46,3712.41 h60
  text "WHITE" at 12563.46,3712.41 h60
  text "OTHER" at 13074.46,3712.41 h60
  text "X" at 12576.46,3568.96 h60
  text "GREEN" at 12694.46,3568.96 h60
  text "OTHER" at 13312.46,3568.96 h60
  text "SOLDER RESIST COLOR:" at 11488.68,3562.1 h60
  text "X" at 12576.46,3414.71 h60
  text "MATTE" at 12694.46,3414.71 h60
  text "SEMI-GLOSS" at 13312,3414.07 h60
  text "IMMERSION GOLD (ENIG)" at 12394.46,3241.94 h60
  text "ENEPIG" at 13732,3234.72 h60
  text "SURFACE FINISH:" at 11333.46,3233.72 h60
  text "X" at 12216.46,3233.72 h60
  text "IMM. TIN/SILVER OR EQUIV" at 11663,3096.4 h60
  text "OTHER" at 13094.46,3092.47 h60
  text "ARRAY/PANEL:" at 11333.46,2937.09 h60
  text "CUT AND TRIM PER M1 BOARD OUTLINE" at 12394.46,2928.87 h60
  text "N.C. ROUTE" at 12394.46,2792.9 h60
  text "X" at 13082.46,2792.9 h60
  text "V. SCORE" at 13260.46,2792.9 h60
  text "CERTIFICATION:" at 11333.46,2663.77 h60
  text "MATERIALS AND WORKMANSHIP FOR ALL PCBS" at 12058.46,2663.77 h60
  text "TO MEET OR EXCEED THE REQUIREMENTS OF:" at 12058.46,2569.71 h60
  text "X" at 11695.97,2441.08 h60
  text "ANSI IPC-A-600F CLASS ->" at 11823.96,2441.08 h60
  text "X" at 13471.97,2441.08 h60
  text "2" at 13581.96,2441.08 h60
  text "1" at 13266.96,2439.58 h60
  text "3" at 13935.96,2439.58 h60
  text "X" at 12507.97,2293.39 h60
  text "RoHS" at 12635.96,2293.39 h60
  text "OTHER" at 13280.36,2293.39 h60
  text "PER ORDER" at 13677.42,2293.39 h60
  text "ALL BOARDS MUST MEET OR EXCEED UL94-V0 REQUIREMENTS." at 11361,2139.57 h60
  text "PCB MUST BEAR THE UL94V-0 UL REGISTERED MATERIAL ID NUMBER" at 11361,2023.5 h60
  text "ADDITIONAL REQUIREMENTS:" at 11333.46,1854.08 h60
  text "MICROSECTION:" at 11408.23,1746.95 h60
  text "YES" at 12313.96,1746.95 h60
  text "REQUIRED" at 13175.46,1602.62 h60
  text "BARE BOARD ELEC. TEST:" at 11408.23,1599.76 h60
  text "NONE" at 12713.96,1599.76 h60
  text "X" at 13057.46,1599.76 h60
  text "PER ORDER" at 13767.46,1599.76 h60
  text "XX MIL VIAS REQUIRE NON-CONDUCTIVE FILL AND PLANARIZE" at 11576.38,1394.82 h59
  text "XX MIL VIAS REQUIRE CONDUCTIVE FILL AND PLANARIZE" at 11584.38,1290.84 h60
  text "OUTER XX MIL TRACES REQUIRE 50 OHM SINGLE-ENDED IMPEDANCE" at 11583.39,1127.46 h58
  text "LAYER 2 & 3 (INNER LAYERS) XX MIL WIDE, XX MIL SPACE / TRACES REQUIRE 100 OHM DIFFERENTIAL IMPEDANCE" at 11575.39,891.74 h60
  text ".Layer_Name" at 577,-858.49 h60
M11 Gerber Information:
  lines w10: -292,-930.17 6308,-930.17 ; -292,-726.83 6310,-726.83 ; -292,-523.5 -292,-1133.5 3713,-1133.5 6310,-1133.5 6310,-523.5 -291.5,-523.5 -291.5,-1133.5 1284,-1133.5 ; 2173,-1133.5 2173,-523.5 ; 3440,-726.83 3440,-523.5 ; 4280,-726.83 4280,-523.5 ; 4902,-1140 4902,-937.17
  text "ALL ARTWORK VIEWED FROM TOP SIDE" at -228.5,-655.67 h60
  text "BOARD #:" at 2248,-655.67 h60
  text ".PRJ_Number" at 2793.5,-655.67 h60
  text "REV:" at 3638,-655.67 h60
  text ".PCB_Rev" at 3929.5,-655.67 h60
  text "SVN REV:" at 4476,-655.67 h60
  text ".VersionControl_RevNumber" at 4982,-655.67 h60
  text "LAYER NAME =" at -228.5,-858.49 h60
  text "TID #:" at 2248,-859 h60
  text ".TID" at 2793.5,-859 h60
  text "PLOT NAME =" at -228.5,-1064.34 h60
  text ".plot_File_Name" at 577,-1064.34 h60
  text "GENERATED    :" at 2250,-1064.34 h60
  text ".Print_Date" at 3119.5,-1064.34 h60
  text ".Print_Time" at 3848.5,-1064.34 h60
  text "TEXAS INSTRUMENTS" at 5113,-1064.34 h60
M12 Stackup:
  drawing of 295 lines, arcs and shapes, not listed
  text "Layer" at 6425.35,6875 h60
  text "Name" at 6835.26,6875 h60
  text "Material" at 7775,6875 h60
  text "Thickness" at 8634.77,6875 h60
  text "Constant" at 9284.6,6875 h60
  text "Board Layer Stack" at 9854.46,6875 h60
  text "1" at 6425.35,6755 h60
  text "Top Overlay" at 6835.26,6755 h60
  text "2" at 6425.35,6635 h60
  text "Top Solder" at 6835.26,6635 h60
  text "Solder Resist" at 7775,6635 h60
  text "0.40mil" at 8634.77,6635 h60
  text "3.5" at 9284.6,6635 h60
  text "3" at 6425.35,6515 h60
  text "Top Layer" at 6835.26,6515 h60
  text "Copper" at 7775,6515 h60
  text "1.40mil" at 8634.77,6515 h60
  text "4" at 6425.35,6395 h60
  text "Dielectric1" at 6835.26,6395 h60
  text "FR-4" at 7775,6395 h60
  text "10.00mil" at 8634.77,6395 h60
  text "4.8" at 9284.6,6395 h60
  text "5" at 6425.35,6275 h60
  text "Signal Layer 1" at 6835.26,6275 h60
  text "Copper" at 7775,6275 h60
  text "1.42mil" at 8634.77,6275 h60
  text "6" at 6425.35,6155 h60
  text "Dielectric 2" at 6835.26,6155 h60
  text "36.00mil" at 8634.77,6155 h60
  text "4.2" at 9284.6,6155 h60
  text "7" at 6425.35,6035 h60
  text "Signal Layer 2" at 6835.26,6035 h60
  text "Copper" at 7775,6035 h60
  text "1.42mil" at 8634.77,6035 h60
  text "8" at 6425.35,5915 h60
  text "Dielectric 3" at 6835.26,5915 h60
  text "10.00mil" at 8634.77,5915 h60
  text "4.2" at 9284.6,5915 h60
  text "9" at 6425.35,5795 h60
  text "Bottom Layer" at 6835.26,5795 h60
  text "Copper" at 7775,5795 h60
  text "1.40mil" at 8634.77,5795 h60
  text "10" at 6425.35,5675 h60
  text "Bottom Solder" at 6835.26,5675 h60
  text "Solder Resist" at 7775,5675 h60
  text "0.40mil" at 8634.77,5675 h60
  text "3.5" at 9284.6,5675 h60
  text "11" at 6425.35,5555 h60
  text "Bottom Overlay" at 6835.26,5555 h60
  text ".Layer_Name" at 577,-858.49 h60
M13 Component Bodies Top:
  text ".Layer_Name" at 577,-858.49 h60
M14 Component Bodies Bottom:
  text ".Layer_Name" at 577,-858.49 h60
M15 Courtyards Top:
  text ".Layer_Name" at 577,-858.49 h60
M16 Courtyards Bottom:
  text ".Layer_Name" at 577,-858.49 h60
Drill Drawing:
  circle w10: c5363.72,2421.72 r27.63
  lines w10: 5336.09,2518.42 5363.72,2532.23 5391.34,2518.42 5377.53,2546.04 5391.34,2573.67 5363.72,2559.86 5336.09,2573.67 5349.9,2546.04 5336.09,2518.42 ; 5336.09,2642.74 5391.34,2642.74 5391.34,2697.99 5336.09,2697.99 5336.09,2642.74 ; 5336.09,2822.31 5391.34,2822.31 5363.72,2767.06 5336.09,2822.31 ; 5336.09,2891.38 5336.09,2905.19 5349.9,2919 5336.09,2932.82 5336.09,2946.63 5349.9,2946.63 5363.72,2932.82 5377.53,2946.63 5391.34,2946.63 5391.34,2932.82 5377.53,2919 5391.34,2905.19 5391.34,2891.38 5377.53,2891.38 5363.72,2905.19 5349.9,2891.38 5336.09,2891.38 ; 5336.09,3029.51 5349.9,3029.51 5363.72,3015.7 5377.53,3029.51 5391.34,3029.51 5377.53,3043.32 5391.34,3057.14 5377.53,3057.14 5363.72,3070.95 5349.9,3057.14 5336.09,3057.14 5349.9,3043.32 5336.09,3029.51 ; 5336.09,3167.64 5363.72,3140.02 5391.34,3167.64 5363.72,3195.27 5336.09,3167.64 ; 5336.09,3264.34 5391.34,3264.34 5391.34,3319.59 5336.09,3319.59 5336.09,3264.34 ; 5336.09,3402.47 5349.9,3402.47 5349.9,3388.66 5377.53,3388.66 5377.53,3402.47 5391.34,3402.47 5391.34,3430.1 5377.53,3430.1 5377.53,3443.91 5349.9,3443.91 5349.9,3430.1 5336.09,3430.1 5336.09,3402.47 ; 5347.14,3275.39 5380.29,3275.39 5380.29,3308.54 5347.14,3308.54 5347.14,3275.39
  lines w12: 5286,2356.8 8517.49,2356.8 ; 5286,3475.68 8517.49,3475.68 ; 5623.86,2232.48 5623.86,3600 ; 5955.86,2232.48 5955.86,3600 ; 6592.43,2232.48 6592.43,3600 ; 6851.57,2232.48 6851.57,3600 ; 7226.72,2232.48 7226.72,3600 ; 7951.05,2232.48 7951.05,3600 ; 5286,2232.48 8517.49,2232.48 8517.49,3600 5286,3600 5286,2232.48
  text "Symbol" at 5360.59,3512.98 h72
  text "Quantity" at 5661.16,3512.98 h72
  text "Finished Hole Size" at 5993.16,3512.98 h72
  text "Plated" at 6629.72,3512.98 h72
  text "Hole Type" at 6888.86,3512.98 h72
  text "Drill Layer Pair" at 7264.02,3512.98 h72
  text "Hole Tolerance" at 7988.35,3512.98 h72
  text "28" at 5661.16,3388.66 h60
  text "7.87mil (0.200mm)" at 5993.16,3388.66 h60
  text "PTH" at 6629.72,3388.66 h60
  text "Round" at 6888.86,3388.66 h60
  text "Top Layer - Bottom Layer" at 7264.02,3388.66 h60
  text "141" at 5661.16,3264.34 h60
  text "10.00mil (0.254mm)" at 5993.16,3264.34 h60
  text "PTH" at 6629.72,3264.34 h60
  text "Round" at 6888.86,3264.34 h60
  text "Top Layer - Bottom Layer" at 7264.02,3264.34 h60
  text "63" at 5661.16,3140.02 h60
  text "11.81mil (0.300mm)" at 5993.16,3140.02 h60
  text "PTH" at 6629.72,3140.02 h60
  text "Round" at 6888.86,3140.02 h60
  text "Top Layer - Bottom Layer" at 7264.02,3140.02 h60
  text "51" at 5661.16,3015.7 h60
  text "40.00mil (1.016mm)" at 5993.16,3015.7 h60
  text "PTH" at 6629.72,3015.7 h60
  text "Round" at 6888.86,3015.7 h60
  text "Top Layer - Bottom Layer" at 7264.02,3015.7 h60
  text "8" at 5661.16,2891.38 h60
  text "40.16mil (1.020mm)" at 5993.16,2891.38 h60
  text "PTH" at 6629.72,2891.38 h60
  text "Round" at 6888.86,2891.38 h60
  text "Top Layer - Bottom Layer" at 7264.02,2891.38 h60
  text "4" at 5661.16,2767.06 h60
  text "49.21mil (1.250mm)" at 5993.16,2767.06 h60
  text "PTH" at 6629.72,2767.06 h60
  text "Round" at 6888.86,2767.06 h60
  text "Top Layer - Bottom Layer" at 7264.02,2767.06 h60
  text "14" at 5661.16,2642.74 h60
  text "51.18mil (1.300mm)" at 5993.16,2642.74 h60
  text "PTH" at 6629.72,2642.74 h60
  text "Round" at 6888.86,2642.74 h60
  text "Top Layer - Bottom Layer" at 7264.02,2642.74 h60
  text "1" at 5661.16,2518.42 h60
  text "63.00mil (1.600mm)" at 5993.16,2518.42 h60
  text "PTH" at 6629.72,2518.42 h60
  text "Round" at 6888.86,2518.42 h60
  text "Top Layer - Bottom Layer" at 7264.02,2518.42 h60
  text "4" at 5661.16,2394.1 h60
  text "125.98mil (3.200mm)" at 5993.16,2394.1 h60
  text "PTH" at 6629.72,2394.1 h60
  text "Round" at 6888.86,2394.1 h60
  text "Top Layer - Bottom Layer" at 7264.02,2394.1 h60
  text "314 Total" at 5661.16,2269.78 h60
  text ".Layer_Name" at 577,-858.49 h60
M17 Embedded Cavity:
  text ".Layer_Name" at 577,-858.49 h60
M18 Embedded Assembly:
  text ".Layer_Name" at 577,-858.49 h60
M19 Embedded Keepout:
  text ".Layer_Name" at 577,-858.49 h60

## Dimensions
0,-400 to 1000,-400 on M2 Board Dimensions
0,0 to 0,3000 on M2 Board Dimensions
0,0 to 3700,0 on M2 Board Dimensions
